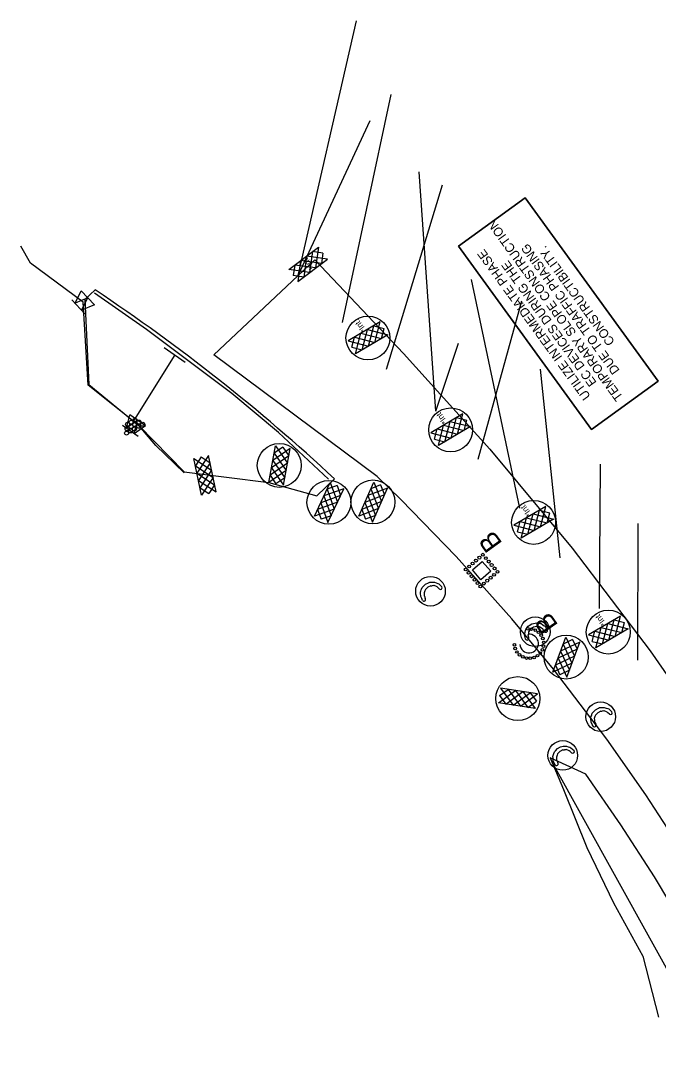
# Model space of a CAD drawing. Extents: x 400935 to 481562, y 415700 to 505362.
# Drawn here: x 475022 to 475516, y 502310 to 503113 of the extents above; entities that cross this region are included whole.
import ezdxf

# ---------------------------------------------------------------- set-up
doc = ezdxf.new("R2010")
doc.units = 0
for name, color, linetype in [('Coir Fiber Wattle with PAM Final CELL', 7, 'Continuous'), ('Drain Terminator Final CELL', 7, 'Continuous'), ('Earth Berm for Slope Drains Final', 7, 'Continuous'), ('Excelsior Wattle Line Style Final', 7, 'Continuous'), ('Label B CG CELL', 7, 'Continuous'), ('Label B Final CELL', 7, 'Continuous'), ('Matting on Slope Note Final CELL', 7, 'Continuous'), ('Old_Level_2', 7, 'Continuous'), ('Prop Grid Mask', 7, 'Continuous'), ('Rock Inlet Sediment Trap Type B Final CELL', 7, 'Continuous'), ('Rock Pipe Inlet Sediment Trap Type B CG CELL', 7, 'Continuous'), ('Rock Silt Check Type A Both CELL', 7, 'Continuous'), ('Rock Silt Check Type A with Matting and PAM CG CELL', 7, 'Continuous'), ('Rock Silt Check Type A with Matting and PAM Final CELL', 7, 'Continuous'), ('Scratch_Level_4', 7, 'Continuous'), ('Slope Drain Final', 7, 'Continuous'), ('Special Sediment Control Fence Section Both CELL', 7, 'Continuous'), ('Temporary Silt Fence Both', 7, 'Continuous')]:
    doc.layers.add(name, color=color, linetype=linetype)

msp = doc.modelspace()

# ---------------------------------------------------------------- linework, layer by layer
at = {"layer": 'Coir Fiber Wattle with PAM Final CELL'}
for p, q in [((475334.95, 502670.51), (475334.38, 502669.18)), ((475335.42, 502671.61), (475334.95, 502670.51)), ((475337.22, 502673.4), (475335.42, 502671.61)), ((475337.22, 502673.4), (475337.23, 502673.41)), ((475339.62, 502674.52), (475337.23, 502673.41)), ((475339.62, 502674.52), (475340.8, 502674.59)), ((475341.91, 502674.65), (475340.8, 502674.59)), ((475341.91, 502674.65), (475342.15, 502674.67)), ((475343.5, 502674.14), (475342.15, 502674.67)), ((475344.53, 502673.73), (475343.5, 502674.14)), ((475345.09, 502673.18), (475344.53, 502673.73)), ((475346.19, 502672.08), (475345.09, 502673.18)), ((475334.38, 502669.18), (475334.42, 502668.15)), ((475334.42, 502668.15), (475334.48, 502666.67)), ((475334.62, 502666.37), (475334.48, 502666.67)), ((475334.62, 502666.37), (475335.39, 502664.67)), ((475415.51, 502638.84), (475415.33, 502637.83)), ((475416.34, 502640.02), (475415.51, 502638.84)), ((475417.04, 502641), (475416.34, 502640.02)), ((475419.19, 502642.36), (475417.04, 502641)), ((475419.19, 502642.36), (475419.2, 502642.36)), ((475421.77, 502642.94), (475419.2, 502642.36)), ((475421.77, 502642.94), (475422.94, 502642.75)), ((475424.04, 502642.57), (475422.94, 502642.75)), ((475424.04, 502642.57), (475424.27, 502642.54)), ((475425.48, 502641.73), (475424.27, 502642.54)), ((475426.39, 502641.12), (475425.48, 502641.73)), ((475426.83, 502640.45), (475426.39, 502641.12)), ((475427.67, 502639.15), (475426.83, 502640.45)), ((475415.33, 502637.83), (475415.07, 502636.37)), ((475415.14, 502636.04), (475415.07, 502636.37)), ((475415.14, 502636.04), (475415.52, 502634.22)), ((475467.35, 502574.17), (475466.92, 502573.05)), ((475469.09, 502576.02), (475467.35, 502574.17)), ((475469.09, 502576.02), (475469.1, 502576.03)), ((475471.44, 502577.23), (475469.1, 502576.03)), ((475471.44, 502577.23), (475472.63, 502577.34)), ((475473.74, 502577.44), (475472.63, 502577.34)), ((475473.74, 502577.44), (475473.97, 502577.46)), ((475475.34, 502576.98), (475473.97, 502577.46)), ((475476.38, 502576.61), (475475.34, 502576.98)), ((475476.96, 502576.08), (475476.38, 502576.61)), ((475478.1, 502575.02), (475476.96, 502576.08)), ((475466.92, 502573.05), (475466.4, 502571.7)), ((475466.4, 502571.7), (475466.48, 502570.68)), ((475466.48, 502570.68), (475466.59, 502569.2)), ((475466.74, 502568.9), (475466.59, 502569.2)), ((475466.74, 502568.9), (475467.56, 502567.23)), ((475437.55, 502543.02), (475437.03, 502541.67)), ((475437.98, 502544.14), (475437.55, 502543.02)), ((475439.72, 502545.99), (475437.98, 502544.14)), ((475439.72, 502545.99), (475439.73, 502546)), ((475442.07, 502547.2), (475439.73, 502546)), ((475442.07, 502547.2), (475443.26, 502547.31)), ((475444.37, 502547.41), (475443.26, 502547.31)), ((475444.37, 502547.41), (475444.6, 502547.43)), ((475445.97, 502546.95), (475444.6, 502547.43)), ((475447.01, 502546.58), (475445.97, 502546.95)), ((475447.59, 502546.04), (475447.01, 502546.58)), ((475448.73, 502544.99), (475447.59, 502546.04)), ((475437.03, 502541.67), (475437.11, 502540.64)), ((475437.11, 502540.64), (475437.22, 502539.17)), ((475437.37, 502538.87), (475437.22, 502539.17)), ((475437.37, 502538.87), (475438.19, 502537.2))]:
    msp.add_line(p, q, dxfattribs=at)
for points in [[(475333.26, 502663.18), (475332.6, 502664.59), (475331.82, 502666.23), (475331.79, 502667.07), (475331.74, 502668.08), (475331.66, 502669.87), (475331.68, 502669.91), (475331.84, 502670.32), (475331.87, 502670.39), (475332.22, 502671.28), (475332.47, 502671.89), (475333.01, 502673.26), (475333.74, 502674), (475335.51, 502675.83), (475335.52, 502675.84), (475337.93, 502676.93), (475338.86, 502677.35), (475340, 502677.38), (475340.23, 502677.39), (475341.19, 502677.42), (475341.92, 502677.43), (475342.1, 502677.44), (475342.46, 502677.45), (475342.47, 502677.45), (475343.87, 502676.88), (475345.11, 502676.37), (475345.86, 502676.07), (475347.13, 502674.85), (475348.25, 502673.78)], [(475413.13, 502633.22), (475412.78, 502634.74), (475412.38, 502636.51), (475412.52, 502637.33), (475412.7, 502638.33), (475413, 502640.1), (475413.02, 502640.13), (475413.27, 502640.5), (475413.31, 502640.56), (475413.85, 502641.35), (475414.22, 502641.9), (475415.05, 502643.12), (475415.91, 502643.69), (475418.04, 502645.1), (475418.05, 502645.1), (475420.63, 502645.65), (475421.64, 502645.86), (475422.75, 502645.65), (475422.98, 502645.61), (475423.93, 502645.43), (475424.65, 502645.29), (475424.81, 502645.25), (475425.17, 502645.19), (475425.18, 502645.18), (475426.43, 502644.33), (475427.53, 502643.57), (475428.2, 502643.11), (475429.18, 502641.65), (475430.04, 502640.36)], [(475465.49, 502565.67), (475464.78, 502567.05), (475463.95, 502568.67), (475463.88, 502569.5), (475463.8, 502570.51), (475463.66, 502572.3), (475463.67, 502572.34), (475463.82, 502572.75), (475463.85, 502572.82), (475464.17, 502573.72), (475464.39, 502574.35), (475464.89, 502575.73), (475465.59, 502576.5), (475467.3, 502578.39), (475467.31, 502578.4), (475469.67, 502579.57), (475470.59, 502580.03), (475471.72, 502580.1), (475471.96, 502580.11), (475472.92, 502580.17), (475473.65, 502580.22), (475473.82, 502580.23), (475474.19, 502580.25), (475474.19, 502580.25), (475475.61, 502579.73), (475476.87, 502579.27), (475477.63, 502578.99), (475478.94, 502577.82), (475480.09, 502576.79)], [(475436.12, 502535.64), (475435.41, 502537.02), (475434.58, 502538.64), (475434.51, 502539.47), (475434.43, 502540.48), (475434.29, 502542.27), (475434.3, 502542.3), (475434.45, 502542.72), (475434.48, 502542.79), (475434.8, 502543.69), (475435.02, 502544.32), (475435.52, 502545.7), (475436.22, 502546.47), (475437.93, 502548.36), (475437.94, 502548.37), (475440.3, 502549.54), (475441.22, 502549.99), (475442.35, 502550.07), (475442.59, 502550.08), (475443.55, 502550.14), (475444.28, 502550.19), (475444.45, 502550.2), (475444.82, 502550.22), (475444.82, 502550.22), (475446.24, 502549.7), (475447.5, 502549.24), (475448.26, 502548.96), (475449.57, 502547.79), (475450.72, 502546.75)]]:
    msp.add_lwpolyline(points, dxfattribs=at)
for centre in [(475339.4, 502670.29), (475420.65, 502638.85), (475471.37, 502572.99), (475442, 502542.95)]:
    msp.add_circle(centre, 11.5, dxfattribs=at)
for centre, radius, start, end in [((475347.15, 502673.01), 1.33, 223.99866, 35.1113), ((475334.32, 502663.93), 1.3, 215.1113, 35.1113), ((475428.81, 502639.85), 1.33, 211.62406, 22.7367), ((475414.33, 502633.72), 1.3, 202.7367, 22.7367), ((475479.03, 502575.98), 1.33, 226.011, 37.12364), ((475466.53, 502566.45), 1.3, 217.12364, 37.12364), ((475449.66, 502545.95), 1.33, 226.011, 37.12364), ((475437.16, 502536.42), 1.3, 217.12364, 37.12364)]:
    msp.add_arc(centre, radius, start, end, dxfattribs=at)
at = {"layer": 'Drain Terminator Final CELL'}
for centre in [(475104.43, 502799.8), (475107.19, 502798.02), (475107.26, 502801.42), (475110.08, 502799.52), (475110.28, 502802.98), (475113.2, 502798.22), (475113.34, 502801.51), (475116.22, 502799.78), (475103.67, 502792.98), (475104.05, 502796.39), (475106.81, 502794.61), (475109.83, 502796.17)]:
    msp.add_circle(centre, 1.55, dxfattribs=at)
at = {"layer": 'Earth Berm for Slope Drains Final'}
msp.add_lwpolyline([(475260.34, 502757.31), (475221.54, 502793.42), (475185.22, 502823.76), (475119.17, 502873.32), (475078.85, 502901.58)], dxfattribs=at)
at = {"layer": 'Excelsior Wattle Line Style Final'}
msp.add_line((475559.8, 502310.34), (475433.65, 502537.77), dxfattribs=at)
at = {"layer": 'Matting on Slope Note Final CELL'}
for p, q in [((475079.31, 502904), (475071.4, 502896.53)), ((475071.4, 502896.53), (475074.55, 502830.72)), ((475074.55, 502830.72), (475113.49, 502798.72)), ((475113.49, 502798.72), (475148.49, 502763.01)), ((475148.49, 502763.01), (475213.92, 502754.73)), ((475213.92, 502754.73), (475251.31, 502744.41)), ((475251.31, 502744.41), (475265.04, 502757.44)), ((475432.16, 502540.95), (475442.46, 502516.47)), ((475442.46, 502516.47), (475460.51, 502471.47)), ((475460.51, 502471.47), (475481.31, 502428.71)), ((475481.31, 502428.71), (475503.97, 502387.33)), ((475503.97, 502387.33), (475516.14, 502340.03))]:
    msp.add_line(p, q, dxfattribs=at)
msp.add_lwpolyline([(475582.9, 502323.13), (475560.94, 502365.71), (475537.66, 502407.62), (475513.04, 502448.75), (475487.09, 502489.07), (475459.86, 502528.53), (475432.16, 502540.95)], dxfattribs=at)
msp.add_arc((474253.94, 501667.1), 1487, 47.15949, 56.28535, dxfattribs=at)
at = {"layer": 'Old_Level_2'}
for p, q in [((475229.49, 502919.78), (475252.53, 502937.22)), ((475252.53, 502937.22), (475250.29, 502921.04)), ((475236.46, 502910.57), (475259.5, 502928.01)), ((475243.32, 502930.25), (475241.04, 502914.04)), ((475259.5, 502928.01), (475243.32, 502930.25)), ((475247.9, 502933.73), (475245.67, 502917.54)), ((475256.01, 502932.64), (475247.9, 502933.73)), ((475256.01, 502932.64), (475254.88, 502924.51)), ((475245.67, 502917.54), (475229.49, 502919.78)), ((475234.06, 502923.18), (475232.95, 502915.18)), ((475250.29, 502921.04), (475234.07, 502923.25)), ((475238.7, 502926.75), (475236.46, 502910.57)), ((475254.88, 502924.51), (475238.7, 502926.75)), ((475241.04, 502914.04), (475232.95, 502915.18)), ((475300.4, 502879.17), (475275.49, 502864.52)), ((475296.3, 502863.36), (475300.4, 502879.17)), ((475286.35, 502857.49), (475290.45, 502873.32)), ((475290.45, 502873.32), (475306.26, 502869.22)), ((475291.3, 502860.42), (475295.44, 502876.26)), ((475295.44, 502876.26), (475303.35, 502874.18)), ((475301.32, 502866.37), (475303.35, 502874.18)), ((475275.49, 502864.52), (475291.3, 502860.42)), ((475278.42, 502859.51), (475280.49, 502867.46)), ((475280.49, 502867.46), (475296.3, 502863.36)), ((475281.35, 502854.56), (475285.45, 502870.38)), ((475306.26, 502869.22), (475281.35, 502854.56)), ((475285.45, 502870.38), (475301.3, 502866.3)), ((475278.42, 502859.51), (475286.35, 502857.49)), ((475364.54, 502807.91), (475339.63, 502793.26)), ((475360.44, 502792.1), (475364.54, 502807.91)), ((475345.48, 502783.3), (475349.58, 502799.11)), ((475349.58, 502799.11), (475365.44, 502795.04)), ((475350.49, 502786.23), (475354.58, 502802.06)), ((475354.58, 502802.06), (475370.4, 502797.96)), ((475355.44, 502789.16), (475359.58, 502805)), ((475359.58, 502805), (475367.49, 502802.92)), ((475365.46, 502795.11), (475367.49, 502802.92)), ((475339.63, 502793.26), (475355.44, 502789.16)), ((475342.56, 502788.25), (475344.63, 502796.2)), ((475344.63, 502796.2), (475360.44, 502792.1)), ((475370.4, 502797.96), (475345.48, 502783.3)), ((475342.56, 502788.25), (475350.49, 502786.23)), ((475428.88, 502736.14), (475403.97, 502721.49)), ((475424.78, 502720.33), (475428.88, 502736.14)), ((475409.82, 502711.53), (475413.92, 502727.35)), ((475413.92, 502727.35), (475429.78, 502723.27)), ((475414.83, 502714.46), (475418.92, 502730.29)), ((475418.92, 502730.29), (475434.73, 502726.19)), ((475419.78, 502717.39), (475423.92, 502733.23)), ((475423.92, 502733.23), (475431.83, 502731.15)), ((475429.79, 502723.34), (475431.83, 502731.15)), ((475403.97, 502721.49), (475419.78, 502717.39)), ((475406.9, 502716.48), (475408.97, 502724.43)), ((475408.97, 502724.43), (475424.78, 502720.33)), ((475434.73, 502726.19), (475409.82, 502711.53)), ((475406.9, 502716.48), (475414.83, 502714.46)), ((475486.78, 502651.08), (475461.87, 502636.42)), ((475477.68, 502632.32), (475481.82, 502648.16)), ((475481.82, 502648.16), (475489.73, 502646.08)), ((475482.68, 502635.27), (475486.78, 502651.08)), ((475464.8, 502631.42), (475466.87, 502639.37)), ((475466.87, 502639.37), (475482.68, 502635.27)), ((475467.72, 502626.47), (475471.82, 502642.28)), ((475492.63, 502641.12), (475467.72, 502626.47)), ((475471.82, 502642.28), (475487.68, 502638.21)), ((475472.73, 502629.4), (475476.82, 502645.22)), ((475476.82, 502645.22), (475492.63, 502641.12)), ((475487.7, 502638.27), (475489.73, 502646.08)), ((475461.87, 502636.42), (475477.68, 502632.32)), ((475464.8, 502631.42), (475472.73, 502629.4))]:
    msp.add_line(p, q, dxfattribs=at)
msp.add_lwpolyline([(475515.99, 502833.13), (475412.92, 502975.47), (475361.15, 502937.99), (475464.22, 502795.65)], close=True, dxfattribs=at)
for centre in [(475290.9, 502866.74), (475355.04, 502795.48), (475419.38, 502723.71), (475477.28, 502638.64)]:
    msp.add_circle(centre, 17.04, dxfattribs=at)
at = {"layer": 'Prop Grid Mask'}
msp.add_lwpolyline([(475464.22, 502795.65), (475361.15, 502937.99), (475412.92, 502975.47), (475515.99, 502833.13)], close=True, dxfattribs=at)
at = {"layer": 'Rock Inlet Sediment Trap Type B Final CELL'}
msp.add_lwpolyline([(475378.52, 502679.25), (475372, 502686.84), (475379.59, 502693.35), (475386.09, 502685.76)], close=True, dxfattribs=at)
for centre in [(475374.68, 502694.07), (475377.33, 502696.35), (475379.99, 502698.63), (475382.27, 502695.97), (475384.55, 502693.32), (475366.71, 502687.23), (475369.36, 502689.51), (475372.02, 502691.79), (475386.83, 502690.66), (475389.11, 502688.01), (475391.39, 502685.35), (475368.99, 502684.58), (475371.27, 502681.92), (475373.55, 502679.26), (475383.42, 502678.51), (475386.07, 502680.79), (475388.73, 502683.07), (475375.83, 502676.61), (475378.11, 502673.95), (475380.76, 502676.23)]:
    msp.add_circle(centre, 1.12, dxfattribs=at)
at = {"layer": 'Rock Pipe Inlet Sediment Trap Type B CG CELL'}
for centre in [(475414.86, 502641.1), (475417.84, 502640.96), (475420.68, 502640.06), (475423.19, 502638.45), (475425.2, 502636.25), (475426.57, 502633.6), (475427.2, 502630.68), (475404.44, 502628.75), (475405.08, 502625.84), (475406.45, 502623.19), (475424.55, 502622.35), (475426.16, 502624.86), (475427.07, 502627.7), (475408.45, 502620.99), (475410.97, 502619.38), (475413.81, 502618.47), (475416.79, 502618.33), (475419.7, 502618.97), (475422.35, 502620.34)]:
    msp.add_circle(centre, 1.01, dxfattribs=at)
msp.add_arc((475415.82, 502629.72), 7.26, 184.84963, 94.84081, dxfattribs=at)
at = {"layer": 'Rock Silt Check Type A Both CELL'}
for p, q in [((475167.24, 502775.6), (475158.28, 502761.94)), ((475173.11, 502747.3), (475167.24, 502775.6)), ((475161.8, 502744.95), (475155.93, 502773.25)), ((475155.93, 502773.25), (475169.58, 502764.29)), ((475161.55, 502774.43), (475157.09, 502767.57)), ((475157.09, 502767.57), (475170.76, 502758.61)), ((475168.41, 502769.92), (475159.45, 502756.26)), ((475161.55, 502774.43), (475168.41, 502769.92)), ((475158.28, 502761.94), (475171.94, 502752.93)), ((475169.58, 502764.29), (475160.63, 502750.58)), ((475170.76, 502758.61), (475161.8, 502744.95)), ((475159.45, 502756.26), (475173.11, 502747.3)), ((475160.69, 502750.54), (475167.44, 502746.11)), ((475171.94, 502752.93), (475167.44, 502746.11))]:
    msp.add_line(p, q, dxfattribs=at)
at = {"layer": 'Rock Silt Check Type A with Matting and PAM CG CELL'}
for p, q in [((475213.92, 502754.73), (475219.25, 502783.13)), ((475219.25, 502783.13), (475228.47, 502769.65)), ((475229.53, 502775.3), (475216.05, 502766.08)), ((475230.6, 502781), (475217.12, 502771.78)), ((475224.9, 502782.09), (475218.17, 502777.44)), ((475218.17, 502777.44), (475227.4, 502763.95)), ((475224.9, 502782.09), (475229.53, 502775.3)), ((475225.27, 502752.6), (475230.6, 502781)), ((475228.47, 502769.65), (475214.98, 502760.38)), ((475217.12, 502771.78), (475226.33, 502758.25)), ((475227.4, 502763.95), (475213.92, 502754.73)), ((475215.02, 502760.32), (475219.57, 502753.66)), ((475216.05, 502766.08), (475225.27, 502752.6)), ((475226.33, 502758.25), (475219.57, 502753.66)), ((475283.75, 502728.57), (475295.39, 502755.02)), ((475300.65, 502752.72), (475293.04, 502749.72)), ((475295.39, 502755.02), (475301.31, 502739.8)), ((475300.65, 502752.72), (475303.62, 502745.06)), ((475303.62, 502745.06), (475288.4, 502739.14)), ((475305.96, 502750.37), (475290.74, 502744.45)), ((475290.74, 502744.45), (475296.64, 502729.18)), ((475293.04, 502749.72), (475298.97, 502734.49)), ((475294.32, 502723.92), (475305.96, 502750.37)), ((475298.97, 502734.49), (475283.75, 502728.57)), ((475301.31, 502739.8), (475286.06, 502733.83)), ((475288.4, 502739.14), (475294.32, 502723.92)), ((475286.09, 502733.76), (475289.01, 502726.24)), ((475296.64, 502729.18), (475289.01, 502726.24)), ((475434.31, 502607.56), (475444.25, 502634.7)), ((475455.09, 502630.73), (475440.28, 502623.86)), ((475449.65, 502632.74), (475442.24, 502629.26)), ((475444.25, 502634.7), (475451.12, 502619.88)), ((475445.16, 502603.59), (475455.09, 502630.73)), ((475449.65, 502632.74), (475453.1, 502625.28)), ((475453.1, 502625.28), (475438.28, 502618.41)), ((475440.28, 502623.86), (475447.13, 502608.99)), ((475442.24, 502629.26), (475449.13, 502614.44)), ((475449.13, 502614.44), (475434.31, 502607.56)), ((475451.12, 502619.88), (475436.29, 502612.96)), ((475438.28, 502618.41), (475445.16, 502603.59)), ((475436.32, 502612.9), (475439.7, 502605.58)), ((475447.13, 502608.99), (475439.7, 502605.58)), ((475392.05, 502583.63), (475405.2, 502593.31)), ((475392.9, 502589.31), (475399.52, 502594.18)), ((475393.78, 502595.05), (475403.47, 502581.9)), ((475422.36, 502590.71), (475393.78, 502595.05)), ((475397.78, 502582.75), (475410.94, 502592.45)), ((475399.52, 502594.18), (475409.2, 502581.03)), ((475403.47, 502581.9), (475416.67, 502591.58)), ((475405.2, 502593.31), (475414.94, 502580.16)), ((475409.2, 502581.03), (475422.36, 502590.71)), ((475410.94, 502592.45), (475420.62, 502579.29)), ((475416.67, 502591.58), (475421.5, 502584.98)), ((475420.62, 502579.29), (475392.05, 502583.63)), ((475392.9, 502589.31), (475397.78, 502582.75)), ((475415, 502580.2), (475421.5, 502584.98))]:
    msp.add_line(p, q, dxfattribs=at)
for centre in [(475222.14, 502767.93), (475294.75, 502739.56), (475444.6, 502619.23), (475407.14, 502587.05)]:
    msp.add_circle(centre, 17.04, dxfattribs=at)
at = {"layer": 'Rock Silt Check Type A with Matting and PAM Final CELL'}
for p, q in [((475249.34, 502728.56), (475261.68, 502754.69)), ((475266.89, 502752.25), (475259.19, 502749.45)), ((475261.68, 502754.69), (475267.19, 502739.31)), ((475266.89, 502752.25), (475269.65, 502744.51)), ((475269.65, 502744.51), (475254.27, 502739)), ((475272.12, 502749.76), (475256.75, 502744.25)), ((475256.75, 502744.25), (475262.24, 502728.83)), ((475259.19, 502749.45), (475264.71, 502734.07)), ((475259.78, 502723.63), (475272.12, 502749.76)), ((475267.19, 502739.31), (475251.79, 502733.76)), ((475254.27, 502739), (475259.78, 502723.63)), ((475264.71, 502734.07), (475249.34, 502728.56)), ((475251.82, 502733.69), (475254.53, 502726.09)), ((475262.24, 502728.83), (475254.53, 502726.09))]:
    msp.add_line(p, q, dxfattribs=at)
msp.add_circle((475260.63, 502739.25), 17.04, dxfattribs=at)
at = {"layer": 'Scratch_Level_4'}
for p, q in [((475236.69, 502915.13), (475281.89, 503112.86)), ((475271.03, 502878.78), (475308.79, 503055.57)), ((475236.7, 502915.13), (475292.54, 503035.56)), ((475343.48, 502810.03), (475330.65, 502995.55)), ((475305.36, 502842.44), (475348.61, 502985.55)), ((475408.6, 502734.83), (475371.32, 502912.23)), ((475376.45, 502772.78), (475410.25, 502895.54)), ((475343.49, 502810.03), (475361.2, 502862.78)), ((475439.94, 502696.2), (475424.63, 502842.59)), ((475470.43, 502656.9), (475471.26, 502768.9)), ((475500.08, 502616.96), (475500.33, 502722.74))]:
    msp.add_line(p, q, dxfattribs=at)
msp.add_lwpolyline([(475533.29, 502471.06), (475506.41, 502512.33), (475476.06, 502555.65), (475434.78, 502609.82), (475402.55, 502648.84), (475359.27, 502697.31), (475316.47, 502741.4), (475297.93, 502759.43), (475171.48, 502853.73), (475249.78, 502927.49), (475318.45, 502854.8), (475385.52, 502780.63), (475449.34, 502703.66), (475509.79, 502624.01), (475566.78, 502541.85)], dxfattribs=at)
at = {"layer": 'Slope Drain Final'}
for p, q in [((475149.21, 502847.66), (475132.82, 502859.11)), ((475141.06, 502853.56), (475108.19, 502801.12))]:
    msp.add_line(p, q, dxfattribs=at)
at = {"layer": 'Special Sediment Control Fence Section Both CELL'}
for p, q in [((475078.72, 502892.35), (475068.45, 502903.27)), ((475071.44, 502885.5), (475061.16, 502896.43)), ((475118.46, 502798.63), (475106.1, 502807.12)), ((475112.8, 502790.38), (475100.44, 502798.87))]:
    msp.add_line(p, q, dxfattribs=at)
for points in [[(475073.59, 502897.81), (475063.73, 502893.69), (475068.45, 502903.27)], [(475078.72, 502892.35), (475068.87, 502888.23), (475073.59, 502897.81)], [(475112.28, 502802.87), (475103.53, 502796.75), (475106.1, 502807.12)], [(475118.46, 502798.63), (475109.71, 502792.51), (475112.28, 502802.87)]]:
    msp.add_lwpolyline(points, dxfattribs=at)
at = {"layer": 'Temporary Silt Fence Both'}
msp.add_lwpolyline([(475148.26, 502762.07), (475148.26, 502762.07), (475148.26, 502762.07), (475126.44, 502783.24), (475113.49, 502798.72), (475073.92, 502830.13), (475070.05, 502894.64), (475029.08, 502924.8), (475021.59, 502937.94)], dxfattribs=at)

# ---------------------------------------------------------------- texts
at = {"layer": 'Label B CG CELL'}
msp.add_text('B', height=15, rotation=124.6685, dxfattribs=at).set_placement((475438.82, 502644.01))
at = {"layer": 'Label B Final CELL'}
msp.add_text('B', height=15, rotation=125.90742, dxfattribs=at).set_placement((475395.57, 502707.48))
at = {"layer": 'Old_Level_2'}
for s, height, rotation, p in [('TEMPORARY SLOPE CONSTRUCTION', 7, 125.90687, (475489.04, 502820.94)), ('UTILIZE INTERMEDIATE PHASE', 7, 125.90687, (475463.85, 502821.63)), ('DUE TO TRAFFIC PHASING', 7, 125.90687, (475486.4, 502841.64)), ('CONSTRUCTIBILITY.', 7, 125.90687, (475482.66, 502863.85)), ('*Int.', 4.746, 127.12364, (475249.74, 502921.81)), ('EC DEVICES DURING THE ', 7, 125.90687, (475468.49, 502832.27)), ('*Int.', 4.746, 127.12364, (475289.99, 502873.06)), ('*Int.', 4.746, 127.12364, (475352.88, 502801.94)), ('*Int.', 4.746, 127.12364, (475418.31, 502730.19)), ('*Int.', 4.746, 127.12364, (475476.18, 502645.34))]:
    msp.add_text(s, height=height, rotation=rotation, dxfattribs=at).set_placement(p)

doc.saveas('drawing.dxf')
